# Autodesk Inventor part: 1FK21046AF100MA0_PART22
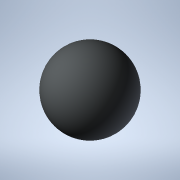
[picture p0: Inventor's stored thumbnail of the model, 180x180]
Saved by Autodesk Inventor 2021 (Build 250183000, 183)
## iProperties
Created: 2025-04
Part Number: 1FK21046AF100MA0_PART22
Material: Generic
Catalog Web Link: www.3dfindit.com
Description: -Servo synchronous motor
Document SubType Name: Modeling
Designer: psAdmin
Mass: 0.137258 g
Surface Area: 1.2868 cm^2
Volume: 0.137258 cm^3
Density: 1 g/cm^3
Appearance: PSOLRGB-212-217-219
Category: PARTsolutions
Title: 1FK21046AF100MA0_PART22
Author: Cadenas PARTsolutions
Comments: Servo synchronous motor
Sending System: PARTsolutions
Preprocessor: ST-DEVELOPER v19.3
PSOL_IDENT_0: {$CADENAS_DATA/23d-libs/siemens_ag/_cat_/4f/2b/1fk21046af100ma0.prj},216 {VTYP=3D},{NB=1FK21046AF100
PSOL_IDENT_1: MA0_PART22},{LINA=1FK21046AF100MA0_PART22},{NN=1FK21046AF100MA0_PART22},{NOPRJ=TRUE},{DATE=19.08.202
PSOL_IDENT_2: 5 14:00:37},{GEOMDATE=30.07.2025 02:01:06},{VERSION=},{LINEID=10},{WBVAR=},{WBNUMERIC=}  {NB=1FK2104
PSOL_IDENT_3: 6AF100MA0_PART22},{LINA=1FK21046AF100MA0_PART22},{KT=DUMMY},{PREVIEW=../../../_pool_/cb/72/p_d211_xx
PSOL_IDENT_4: _00434j.png},{DESCSHORT=SIMOTICS S-1FK2 HD, SINAMICS S210 3AC 400V-480V, 3.2 Nm, 3000 rpm},{DESCLONG=
PSOL_IDENT_5: SIMOTICS S-1FK2 HD servo motor M0=3.2 Nm; PN = 1 kW at nN=3000 rpm (380-480 V); PN = 0.5 kW at nN=15
PSOL_IDENT_6: 00 rpm (200-240 V); with holding brake; degree of protection IP64; cylindrical shaft D19x40mm; absol
PSOL_IDENT_7: ute encoder 22-bit + 12-bit multiturn (encoder AM22DQC); with OCC interface; plug size M17, rotatabl
PSOL_IDENT_8: e; SIMOTICS S-1FK2 servomotorfor a wide range of uses in industrial environments. SIMOTICS S‑1FK2 se
PSOL_IDENT_9: rvomotors are compact synchronous motors with a high dynamic performance that set themselves apart a
PSOL_IDENT_10: s a result of their high power density, degree of protection and overload capability. The motors are
PSOL_IDENT_11: available in two variants: as High Dynamic variant (highest dynamic performance as a result of the
PSOL_IDENT_12: low intrinsic moment of inertia for applications demanding a high dynamic performance with low moved
PSOL_IDENT_13: masses) - and as Compact variant (precise and stable closed-loop control for medium up to large mov
PSOL_IDENT_14: ed masses as a result of a medium intrinsic moment of inertia). SIMOTICSS‑1FK2 servomotors fully exp
PSOL_IDENT_15: loit their strengths in a system with the SINAMICSS210 frequency converter and simple connection usi
PSOL_IDENT_16: ng the one cable connection (OCC). Advantages include the short control and positioning times, fast
PSOL_IDENT_17: and precise correction of disturbing quantities as well as stable control with a high dynamic perfor
PSOL_IDENT_18: mance. The servo motors can be configured to address a wide range of requirements. For example with
PSOL_IDENT_19: and without holding brake, IP64 or IP65 degree of protection, singleturn or multiturn absolute encod
PSOL_IDENT_20: ers - to name just a few. Further, the servomotors are available in different shaft heights extendin
PSOL_IDENT_21: g from 20 to 100. A shaft sealing ring is available to achieve an IP65 degree of protection and for
PSOL_IDENT_22: subsequent mounting at the motor or as spare part. SIMOTICS - the optimum motor for each and every m
PSOL_IDENT_23: otion control application.},{INTNO=195125049673},{SUPPLIERALTNO=1FK2104-6AF10-0MA0},{MANUID=1FK21046
PSOL_IDENT_24: AF100MA0},{MANUNAME=Siemens},{MANUTYPEDESC=Synchronous motor 1FK2-HD 3.2 NM},{AAU732=SIMOTICS},{AAO0
PSOL_IDENT_25: 57=S-1FK2},{AAU734=SIMOTICS S-1FK2 HD servo motor M0=3.2 Nm; PN = 1 kW at nN=3000 rpm (380-480 V); P
PSOL_IDENT_26: N = 0.5 kW at nN=1500 rpm (200-240 V); with holding brake; degree of protection IP64; cylindrical sh
PSOL_IDENT_27: aft D19x40mm; absolute encoder 22-bit + 12-bit multiturn (encoder AM22DQC); with OCC interface; plug
PSOL_IDENT_28: size M17, rotatable;},{AAW338=Synchronous motor 1FK2-HD 3.2 NM},{AAO742=SIMOTICS},{AAO663=404294869
PSOL_IDENT_29: 4534},{NOCUPEROU=1},{PRICEQUANTITY=1},{QUANTITYMIN=1},{QUANTITYINT=1},{CTN=85015220},{COO=DE},{AAO67
PSOL_IDENT_30: 6=1FK2104-6AF10-0MA0},{AAO677=Siemens AG},{ORDERUNIT=C62},{CONTENTUNIT=C62}
NB: 1FK21046AF100MA0_PART22
NT: Servo synchronous motor
NBSYN: $MANUID._PART22
LINA: 1FK21046AF100MA0_PART22
CATALOG: SIEMENS
PREVIEW: ../../../_pool_/cb/72/p_d211_xx_00434j.png
DESCSHORT: SIMOTICS S-1FK2 HD, SINAMICS S210 3AC 400V-480V, 3.2 Nm, 3000 rpm
DESCLONG: SIMOTICS S-1FK2 HD servo motor M0=3.2 Nm; PN = 1 kW at nN=3000 rpm (380-480 V); PN = 0.5 kW at nN=1500 rpm (200-240 V); with holding brake; degree of protection
INTNO: 195125049673
SUPPLIERALTNO: 1FK2104-6AF10-0MA0
MANUID: 1FK21046AF100MA0
MANUNAME: Siemens
MANUTYPEDESC: Synchronous motor 1FK2-HD 3.2 NM
AAU732: SIMOTICS
AAO057: S-1FK2
AAU734: SIMOTICS S-1FK2 HD servo motor M0=3.2 Nm; PN = 1 kW at nN=3000 rpm (380-480 V); PN = 0.5 kW at nN=1500 rpm (200-240 V); with holding brake; degree of protection
AAW338: Synchronous motor 1FK2-HD 3.2 NM
AAO742: SIMOTICS
AAO663: 4042948694534.0
NOCUPEROU: 1
PRICEQUANTITY: 1
QUANTITYMIN: 1
QUANTITYINT: 1
CTN: 85015220
COO: DE
ARTICLENO: 1FK21046AF100MA0_PART22
BOMINFO: 1FK21046AF100MA0_PART22
CREATOR: CADENAS GmbH
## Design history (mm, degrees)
feature "2025_04_17_14_59_39_0177"
body "Solid1"
